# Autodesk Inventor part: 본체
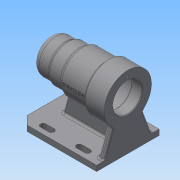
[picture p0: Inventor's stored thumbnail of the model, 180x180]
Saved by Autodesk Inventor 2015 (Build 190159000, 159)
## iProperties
Created: 2017-09
Part Number: 본체
Material: 일반
Document SubType Name: Modeling
Designer: owner
Density: 1 g/cm^3
Appearance: 기본값
Author: owner
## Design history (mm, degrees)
sketch "스케치1"
  geometry: C1 r 34 at (0, 0); 1 further point
  constraints: 1 centre point, 1 coincident
  dimensions: "d0" = 68 diameter of C1
extrude "돌출1" new body sketch "스케치1" distance "d1" = 28; taper "d2" = 0 deg
sketch "스케치2"
  geometry: C1 r 34 at (0, 0) reference; C2 r 30 at (0, 0)
  constraints: 1 centre point, 1 coincident
  dimensions: "d3" = 60 diameter of C2
extrude "돌출2" join sketch "스케치2" distance "d4" = 39; taper "d5" = 0 deg
sketch "스케치3"
  geometry: C1 r 30 at (0, 0) reference; C2 r 27 at (0, 0)
  constraints: 1 centre point, 1 coincident
  dimensions: "d6" = 54 diameter of C2
extrude "돌출3" join sketch "스케치3" distance "d7" = 20; taper "d8" = 0 deg
sketch "스케치4"
  geometry: C1 r 27 at (0, 0) reference; C2 r 25 at (0, 0)
  constraints: 1 centre point, 1 coincident
  dimensions: "d9" = 50 diameter of C2
extrude "돌출4" join sketch "스케치4" distance "d10" = 25; taper "d11" = 0 deg
node "작업 평면1"
sketch "스케치5"
  geometry: L1 (0, -34)-(0, 34) reference; L2 (-112, 25)-(-112, -25) reference; L3 (-112, 45)-(0, 45); L4 (0, 45)-(0, -45); L5 (0, -45)-(-112, -45); L6 (-112, -45)-(-112, 45); L7 (-112, 0)-(0, 0); L8 (-112, 0)-(0, 0); 1 further point
  constraints: 12 end point, 5 midpoint, 2 horizontal, 2 parallel, 1 perpendicular
  dimensions: "d13" = 112 distance of L3.start L3.end; "d14" = 90 distance of L3.end L4.end
extrude "돌출5" join sketch "스케치5" distance "d15" = 8; taper "d16" = 0 deg
sketch "스케치6"
  geometry: L1 (-45, -62)-(45, -62) reference; L2 (0, 0)-(0, -62); L3 (-34, 0)-(34, 0); L4 (-35, -62)-(-12.434, 0); L5 (35, -62)-(12.434, 0); L6 (-12.434, 0)-(12.434, 0); L7 (-35, -62)-(35, -62); A1 r 34 centre (0, 0) between (-34, 0) and (34, 0) reference; 1 further point
  constraints: 12 end point, 5 point on line, 2 collinear, 2 midpoint, 2 point on circle, 1 equal length, 1 horizontal
  dimensions: "d17" = 10 distance of L4.start L1.start; "d18" = 10 distance of L1.end L5.start; "d19" = 110 deg angle of L1 L5
extrude "돌출6" join sketch "스케치6" distance "d20" = 8; taper "d21" = 0 deg
sketch "스케치7"
  geometry: L1 (112, -70)-(0, -70) reference; L2 (112, -70)-(112, -62) reference; L3 (0, -62)-(112, -62) reference; L4 (0, -70)-(0, -62) reference; L5 (112, -25)-(112, 25) reference; L6 (87, 25)-(87, -25) reference; L7 (112, 0)-(0, 0); L8 (73.387, 0)-(90, -62); L9 (90, -62)-(0, -62); L10 (73.387, 0)-(0, 0); L11 (0, 0)-(0, -62)
  constraints: 10 end point, 2 collinear, 2 point on line, 1 horizontal, 1 midpoint, 1 vertical
  dimensions: "d22" = 22 distance of L8.end L2.end; "d23" = 105 deg angle of L3 L8
extrude "돌출7" join sketch "스케치7" stored distance "d24" = 8; taper "d25" = 0 deg
sketch "스케치8"
  geometry: L1 (0, -45)-(112, -45) reference; L2 (112, -45)-(112, 45) reference; L3 (112, 45)-(0, 45) reference; L4 (112, 0)-(0, 0); L5 (112, -34)-(0, -34); L6 (24, -45)-(24, 45); L7 (36, -45)-(36, 45); L8 (76, -45)-(76, 45); L9 (88, -45)-(88, 45); L10 (88, -38)-(76, -38); L11 (88, -30)-(76, -30); L12 (36, -38)-(24, -38); L13 (36, -30)-(24, -30); A1 r 4 centre (24, -34) between (24, -30) and (24, -38); A2 r 4 centre (36, -34) between (36, -38) and (36, -30); A3 r 4 centre (76, -34) between (76, -30) and (76, -38); A4 r 4 centre (88, -34) between (88, -38) and (88, -30)
  constraints: 25 point on line, 20 end point, 8 point on circle, 4 centre point, 3 perpendicular, 2 horizontal, 1 midpoint, 1 vertical
  dimensions: "d26" = 34 distance of L5.start L4.start; "d27" = 24 distance of L1.start L6.start; "d28" = 12 distance of L6.start L7.start; "d29" = 40 distance of L8.start L7.start; "d30" = 12 distance of L9.start L8.start; "d31" = 8 diameter of A1; "d32" = 8 diameter of A2; "d33" = 8 diameter of A3; "d34" = 8 diameter of A4
extrude "돌출8" cut sketch "스케치8" distance "d35" = 20; taper "d36" = 0 deg
chamfer "모따기1" distance "d37" = 12; stored, may be unused: second distance "d38" = 2, angle "d39" = 45 deg
sketch "스케치9"
  geometry: C1 r 21 at (0, 0); A1 r 34 centre (0, 0) between (21.9, -26.008) and (-21.9, -26.008) reference
  constraints: 1 centre point, 1 coincident
  dimensions: "d40" = 42 diameter of C1
extrude "돌출9" cut sketch "스케치9" distance "d41" = 15; taper "d42" = 0 deg
sketch "스케치10"
  geometry: C1 r 21 at (0, 0) reference; C2 r 24 at (0, 0)
  constraints: 1 centre point, 1 coincident
  dimensions: "d43" = 48 diameter of C2
extrude "돌출10" cut sketch "스케치10" distance "d44" = 54; taper "d45" = 0 deg
sketch "스케치11"
  geometry: C1 r 24 at (0, 0) reference; C2 r 21 at (0, 0)
  constraints: 1 centre point, 1 coincident
  dimensions: "d46" = 42 diameter of C2
extrude "돌출11" cut sketch "스케치11" distance "d47" = 12; taper "d48" = 0 deg
sketch "스케치12"
  geometry: C1 r 21 at (0, 0) reference; C2 r 17.5 at (0, 0)
  constraints: 1 centre point, 1 coincident
  dimensions: "d49" = 35 diameter of C2
extrude "돌출12" cut sketch "스케치12" distance "d50" = 18; taper "d51" = 0 deg
sketch "스케치13"
  geometry: C1 r 17.5 at (0, 0) reference; C2 r 16 at (0, 0)
  constraints: 1 centre point, 1 coincident
  dimensions: "d52" = 32 diameter of C2
extrude "돌출13" cut sketch "스케치13" distance "d53" = 4; taper "d54" = 0 deg
sketch "스케치14"
  geometry: C1 r 16 at (0, 0) reference; C2 r 10.5 at (0, 0)
  constraints: 1 centre point, 1 coincident
  dimensions: "d55" = 21 diameter of C2
extrude "돌출14" cut sketch "스케치14" distance "d56" = 3; taper "d57" = 0 deg
fillet "모깎기3" dims "d60" = 3
fillet "모깎기4" dims "d61" = 3
fillet "모깎기5" dims "d62" = 1
fillet "모깎기6" dims "d63" = 9
chamfer "모따기2" distance "d64" = 1; stored, may be unused: second distance "d65" = 2, angle "d66" = 45 deg
fillet "모깎기7" dims "d67" = 3
fillet "모깎기8" dims "d68" = 3
fillet "모깎기9" dims "d69" = 3
fillet "모깎기10" dims "d70" = 0.3
fillet "모깎기11" dims "d71" = 3
fillet "모깎기12" dims "d72" = 3
sketch "스케치15" dims "d73" = 52
  geometry: L1 (0, 0)-(0, 26); C1 r 22 at (0, 0) reference; 1 further point
  constraints: 2 coincident, 2 end point, 1 vertical, 1 vertical alignment, 2 other
hole "구멍1" sketch "스케치15" at (0, 26) diameter "d74" = 3.242; stored, may be unused: countersink angle "d78" = 90 deg, drill point angle "d80" = 118 deg; dims "d75" = 8, "d76" = 4, "d77" = 2, "d79" = 11
node "작업축1"
fillet "모깎기13" dims "d84" = 3
node "작업 평면2"
sketch "스케치16"
  geometry: L1 (0, 34)-(0, -25.254) reference; 2 further points
  constraints: 1 horizontal alignment, 1 other
  dimensions: "d86" = 48 distance from line of point (-48, 0) L1
feature "엠보싱1" sketch "스케치16" dims "d0" = 68, "d87" = 0.5, "d88" = 0
node "솔리드1"
mirror "대칭1"
pattern_circular "원형 패턴1" dims angle "d82" = 360 deg
node "투영된 루프1"
node "투영된 루프2"
